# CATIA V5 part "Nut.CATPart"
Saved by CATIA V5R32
Part number: nut
Bounding box of the stored display mesh (mm): x -13.856 to 13.856, y 0 to 9, z -12 to 12
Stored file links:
  D:\PROJECTS\Project 2022\CATIA V5 6R 2022\Resources\Part Files\c14_catia_v5_6r2022_prt\c14-catia-v5-6r2022-figr-14-26 & 27\Part & Asm\Nut.CATPart
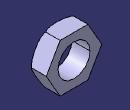
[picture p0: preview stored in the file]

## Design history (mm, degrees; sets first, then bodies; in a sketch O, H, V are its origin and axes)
Body1 (main body)
  Sketch1 on zx-plane, origin (0, 0, 0), H (-1, 0, 0), V (0, 0, 1)
    circle A1 centre (0, 0) radius 8
    construction circle A2 centre (0, 0) radius 12
    point P1 (-6.9282, -12)
    point P2 (6.9282, -12)
    point P3 (13.8564, 0)
    point P4 (6.9282, 12)
    point P5 (-6.9282, 12)
    point P6 (-13.8564, 0)
    point P7 (0, -12)
    line L1 (-6.9282, -12) -> (6.9282, -12)
    line L2 (6.9282, -12) -> (13.8564, 0)
    line L3 (13.8564, 0) -> (6.9282, 12)
    line L4 (6.9282, 12) -> (-6.9282, 12)
    line L5 (-6.9282, 12) -> (-13.8564, 0)
    line L6 (-13.8564, 0) -> (-6.9282, -12)
    construction line L7 (0, 0) -> (0, -12)
    construction circle A3 centre (0, 0) radius 13.8564
    construction arc A4 centre (-6.9282, 12) radius 13.8564 from (6.9282, 12) to (-13.8564, 0) cw
    construction arc A5 centre (6.9282, -12) radius 13.8564 from (13.8564, 0) to (-6.9282, -12) ccw
    radius A1 = 8
    radius A2 = 12
    coincidence: P7 A2, A3 P1, A3 P2, A3 P3, A3 P4, A3 P5, A3 P6, A4 O, A5 O
    vertical: L7 V
    midpoint: P7 L1
    parallelism: L1 L4
  Pad1: profile Sketch1, direction (0, 1, 0), length 9
  Sketch2 on xy-plane, origin (0, 0, 0), H (1, 0, 0), V (0, 1, 0)
    projected line E1 (10.7061, 0) -> (13.8564, 0) from edge of Pad1
    point P1 (13.8564, 0)
    projected line E2 (13.8564, 0) -> (13.8564, 1.8188) from edge of Pad1
    point P2 (13.8564, 0)
    arc A1 centre (10.7061, 3.6376) radius 3.6376 from (10.7061, 0) to (13.8564, 1.8188) ccw
    coincidence: P1 P2
    tangency: A1 E1
  Groove1: profile Sketch2, axis axis of face of Pad1, angle 360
